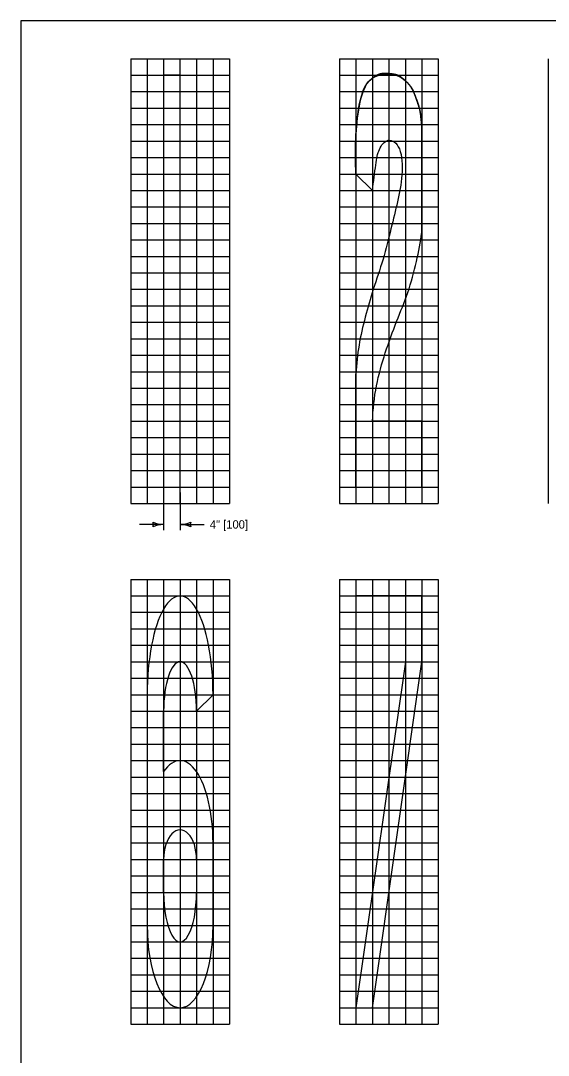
# Model space of a CAD drawing. Extents: x 49991.4 to 50021, y 49987.6 to 50011.4.
# Drawn here: x 50000.34 to 50004.12, y 50003.84 to 50011.26 of the extents above; entities that cross this region are included whole.
import ezdxf

# ---------------------------------------------------------------- set-up
doc = ezdxf.new("R2010")
doc.units = 0
for name, color, linetype in [('Level 1', 7, 'Continuous'), ('Level 2', 7, 'Continuous'), ('Level 3', 7, 'Continuous'), ('Level 9', 7, 'Continuous')]:
    doc.layers.add(name, color=color, linetype=linetype)

msp = doc.modelspace()

# ---------------------------------------------------------------- linework, layer by layer
at = {"layer": 'Level 1'}
for p, q in [((50001.3611, 50010.8724), (50001.3611, 50007.9192)), ((50001.4792, 50010.8724), (50001.3611, 50010.8724)), ((50001.4792, 50007.9192), (50001.4792, 50010.8724)), ((50003.2133, 50009.7442), (50003.2134, 50010.3999)), ((50002.7409, 50010.1636), (50002.859, 50010.0455)), ((50002.7409, 50008.7301), (50002.7409, 50007.9192)), ((50003.2134, 50008.3916), (50002.8591, 50008.3916)), ((50003.2134, 50007.9192), (50003.2134, 50008.3916)), ((50002.7409, 50007.9192), (50003.2134, 50007.9192)), ((50003.2134, 50007.1392), (50002.7409, 50007.1392)), ((50002.7409, 50007.1392), (50002.7409, 50006.6667)), ((50003.2134, 50006.6667), (50003.2134, 50007.1392)), ((50003.0953, 50006.6667), (50002.7409, 50004.1861)), ((50002.7409, 50006.6667), (50003.0953, 50006.6667)), ((50002.8591, 50004.1861), (50003.2134, 50006.6667)), ((50001.243, 50006.4304), (50001.243, 50004.7767)), ((50001.5973, 50006.3123), (50001.7155, 50006.4304)), ((50001.3611, 50005.8788), (50001.3611, 50006.3123)), ((50001.7155, 50004.7767), (50001.7155, 50005.3673)), ((50001.3611, 50005.0129), (50001.3611, 50005.2492)), ((50001.5973, 50005.2492), (50001.5973, 50005.0129)), ((50002.7409, 50004.1861), (50002.8591, 50004.1861))]:
    msp.add_line(p, q, dxfattribs=at)
msp.add_lwpolyline([(50008.6146, 50011.2628), (50000.3356, 50011.2628), (50000.3356, 50000.0624), (50008.6146, 50000.0624)], close=True, dxfattribs=at)
for centre, major_axis, ratio, start_param, end_param in [((50001.4792, 50006.4304), (0, -0.7087), 0.333309, 1.570796, 4.712389), ((50001.4792, 50006.3123), (0, 0.3544), 0.333309, 4.712389, 7.853866), ((50001.4792, 50005.3673), (0, -0.5906), 0.399971, 1.570796, 3.665191), ((50001.4792, 50005.2492), (0, 0.2125), 0.555853, 4.712389, 7.853982), ((50001.4792, 50005.0129), (0, 0.3544), 0.333309, 1.570796, 4.712389), ((50001.4792, 50004.7767), (0, 0.5906), 0.399971, 1.570838, 4.712389)]:
    msp.add_ellipse(centre, major_axis=major_axis, ratio=ratio, start_param=start_param, end_param=end_param, dxfattribs=at)
for points, degree in [([(50002.856, 50010.8496), (50002.7998, 50010.808), (50002.7555, 50010.6449), (50002.7428, 50010.4992), (50002.7393, 50010.4209)], 3), ([(50002.9807, 50010.883), (50002.9367, 50010.8868), (50002.8899, 50010.8746), (50002.856, 50010.8496)], 2), ([(50003.0955, 50010.832), (50003.0647, 50010.8602), (50003.024, 50010.8793), (50002.9807, 50010.883)], 2), ([(50003.1795, 50010.6859), (50003.1631, 50010.733), (50003.1393, 50010.7918), (50003.0955, 50010.832)], 2), ([(50003.2073, 50010.5672), (50003.2017, 50010.616), (50003.1931, 50010.647), (50003.1795, 50010.6859)], 2), ([(50003.2134, 50010.3999), (50003.2147, 50010.467), (50003.2122, 50010.524), (50003.2073, 50010.5672)], 2), ([(50002.7393, 50010.4209), (50002.7355, 50010.336), (50002.7355, 50010.2494), (50002.7409, 50010.1636)], 2), ([(50002.859, 50010.0455), (50002.8675, 50010.1052), (50002.8837, 50010.2485), (50002.9012, 50010.3398), (50002.9649, 50010.4307), (50003.068, 50010.3688), (50003.0785, 50010.1518), (50003.0402, 50009.9647), (50002.9935, 50009.7776), (50002.9386, 50009.5497), (50002.8617, 50009.3355), (50002.8067, 50009.1384), (50002.7577, 50008.9357), (50002.7448, 50008.8021), (50002.7409, 50008.7301)], 3), ([(50002.8591, 50008.3916), (50002.8627, 50008.475), (50002.8816, 50008.649), (50002.9489, 50008.8823), (50003.0319, 50009.1117), (50003.1174, 50009.3075), (50003.1776, 50009.5413), (50003.2041, 50009.6768), (50003.2133, 50009.7442)], 3)]:
    msp.add_open_spline(points, degree=degree, dxfattribs=at)
at = {"layer": 'Level 3'}
for p, q in [((50001.3611, 50007.8792), (50001.3611, 50007.6111)), ((50001.4792, 50007.8792), (50001.4792, 50007.6111)), ((50001.3611, 50007.6511), (50001.1877, 50007.6511)), ((50001.4792, 50007.6511), (50001.6526, 50007.6511))]:
    msp.add_line(p, q, dxfattribs=at)
for centre, radius, start, end in [((50001.3702, 50007.8733), 0.2223, 247.45601, 267.63952), ((50001.2329, 50007.6511), 0.0548, 342.13882, 17.86118), ((50001.3726, 50007.4184), 0.233, 92.82731, 112.07716), ((50001.4677, 50007.8838), 0.233, 272.82731, 292.07716), ((50001.47, 50007.429), 0.2223, 67.45601, 87.63952), ((50001.6074, 50007.6511), 0.0548, 162.13882, 197.86118)]:
    msp.add_arc(centre, radius, start, end, dxfattribs=at)
at = {"layer": 'Level 9'}
for p, q in [((50001.1249, 50010.9905), (50001.1249, 50007.8011)), ((50001.1249, 50010.9905), (50001.8335, 50010.9905)), ((50001.243, 50010.9905), (50001.243, 50007.8011)), ((50001.3611, 50010.9905), (50001.3611, 50007.8011)), ((50001.4792, 50007.8011), (50001.4792, 50010.9905)), ((50001.5973, 50010.9905), (50001.5973, 50007.8011)), ((50001.7154, 50010.9905), (50001.7154, 50007.8011)), ((50001.8335, 50010.9905), (50001.8335, 50007.8011)), ((50002.6228, 50010.9905), (50002.6228, 50007.8011)), ((50002.6228, 50010.9905), (50003.3315, 50010.9905)), ((50002.7409, 50010.9905), (50002.7409, 50007.8011)), ((50002.859, 50010.9905), (50002.859, 50007.8011)), ((50002.9771, 50010.9905), (50002.9771, 50007.8011)), ((50003.0953, 50010.9905), (50003.0953, 50007.8011)), ((50003.2134, 50010.9905), (50003.2134, 50007.8011)), ((50003.3315, 50010.9905), (50003.3315, 50007.8011)), ((50004.1207, 50010.9905), (50004.1207, 50007.8011)), ((50001.1248, 50010.8724), (50001.8336, 50010.8724)), ((50002.6228, 50010.8723), (50003.3315, 50010.8723)), ((50001.1248, 50010.7542), (50001.8336, 50010.7542)), ((50002.6228, 50010.7542), (50003.3315, 50010.7542)), ((50001.1248, 50010.6361), (50001.8336, 50010.6361)), ((50002.6228, 50010.6361), (50003.3315, 50010.6361)), ((50001.1248, 50010.518), (50001.8336, 50010.518)), ((50002.6228, 50010.518), (50003.3315, 50010.518)), ((50001.1248, 50010.3999), (50001.8336, 50010.3999)), ((50002.6228, 50010.3999), (50003.3315, 50010.3999)), ((50003.2134, 50010.3999), (50003.2133, 50009.7442)), ((50001.1248, 50010.2817), (50001.8336, 50010.2817)), ((50002.6228, 50010.2817), (50003.3315, 50010.2817)), ((50001.1248, 50010.1636), (50001.8336, 50010.1636)), ((50002.6228, 50010.1636), (50003.3315, 50010.1636)), ((50002.7409, 50010.1636), (50002.859, 50010.0455)), ((50001.1248, 50010.0455), (50001.8336, 50010.0455)), ((50002.6228, 50010.0455), (50003.3315, 50010.0455)), ((50001.1248, 50009.9274), (50001.8336, 50009.9274)), ((50002.6228, 50009.9274), (50003.3315, 50009.9274)), ((50001.1248, 50009.8092), (50001.8336, 50009.8092)), ((50002.6228, 50009.8092), (50003.3315, 50009.8092)), ((50001.1248, 50009.6911), (50001.8336, 50009.6911)), ((50002.6228, 50009.6911), (50003.3315, 50009.6911)), ((50001.1248, 50009.573), (50001.8336, 50009.573)), ((50002.6228, 50009.573), (50003.3315, 50009.573)), ((50001.1248, 50009.4549), (50001.8336, 50009.4549)), ((50002.6228, 50009.4549), (50003.3315, 50009.4549)), ((50001.1248, 50009.3367), (50001.8336, 50009.3367)), ((50002.6228, 50009.3367), (50003.3315, 50009.3367)), ((50001.1248, 50009.2186), (50001.8336, 50009.2186)), ((50002.6228, 50009.2186), (50003.3315, 50009.2186)), ((50001.1248, 50009.1005), (50001.8336, 50009.1005)), ((50002.6228, 50009.1005), (50003.3315, 50009.1005)), ((50001.1248, 50008.9824), (50001.8336, 50008.9824)), ((50002.6228, 50008.9824), (50003.3315, 50008.9824)), ((50001.1248, 50008.8642), (50001.8336, 50008.8642)), ((50002.6228, 50008.8642), (50003.3315, 50008.8642)), ((50001.1248, 50008.7461), (50001.8336, 50008.7461)), ((50002.6228, 50008.7461), (50003.3315, 50008.7461)), ((50002.7409, 50007.9192), (50002.7409, 50008.7301)), ((50001.1248, 50008.628), (50001.8336, 50008.628)), ((50002.6228, 50008.628), (50003.3315, 50008.628)), ((50001.1248, 50008.5099), (50001.8336, 50008.5099)), ((50002.6228, 50008.5099), (50003.3315, 50008.5099)), ((50001.1248, 50008.3917), (50001.8336, 50008.3917)), ((50002.6228, 50008.3917), (50003.3315, 50008.3917)), ((50003.2134, 50008.3916), (50002.8591, 50008.3916)), ((50003.2134, 50007.9192), (50003.2134, 50008.3916)), ((50001.1248, 50008.2736), (50001.8336, 50008.2736)), ((50002.6228, 50008.2736), (50003.3315, 50008.2736)), ((50001.1248, 50008.1555), (50001.8336, 50008.1555)), ((50002.6228, 50008.1555), (50003.3315, 50008.1555)), ((50001.1248, 50008.0374), (50001.8336, 50008.0374)), ((50002.6228, 50008.0374), (50003.3315, 50008.0374)), ((50001.1248, 50007.9192), (50001.8336, 50007.9192)), ((50001.3611, 50007.9192), (50001.4792, 50007.9192)), ((50002.6228, 50007.9192), (50003.3315, 50007.9192)), ((50002.7409, 50007.9192), (50003.2134, 50007.9192)), ((50001.1248, 50007.8011), (50001.8336, 50007.8011)), ((50002.6228, 50007.8011), (50003.3315, 50007.8011)), ((50001.1249, 50007.2573), (50001.1249, 50004.0679)), ((50001.1249, 50007.2573), (50001.8336, 50007.2573)), ((50001.243, 50007.2573), (50001.243, 50004.0679)), ((50001.3611, 50007.2573), (50001.3611, 50004.0679)), ((50001.4792, 50007.2573), (50001.4792, 50004.0679)), ((50001.5973, 50007.2573), (50001.5973, 50004.0679)), ((50001.7155, 50007.2573), (50001.7155, 50004.0679)), ((50001.8336, 50007.2573), (50001.8336, 50004.0679)), ((50002.6228, 50007.2573), (50002.6228, 50004.0679)), ((50002.6228, 50007.2573), (50003.3315, 50007.2573)), ((50002.7409, 50007.2573), (50002.7409, 50004.0679)), ((50002.8591, 50007.2573), (50002.8591, 50004.0679)), ((50002.9772, 50007.2573), (50002.9772, 50004.0679)), ((50003.0953, 50007.2573), (50003.0953, 50004.0679)), ((50003.2134, 50007.2573), (50003.2134, 50004.0679)), ((50003.3315, 50007.2573), (50003.3315, 50004.0679)), ((50001.1249, 50007.1392), (50001.8336, 50007.1392)), ((50002.6228, 50007.1392), (50003.3315, 50007.1392)), ((50001.1249, 50007.0211), (50001.8336, 50007.0211)), ((50002.6228, 50007.0211), (50003.3315, 50007.0211)), ((50001.1249, 50006.9029), (50001.8336, 50006.9029)), ((50002.6228, 50006.9029), (50003.3315, 50006.9029)), ((50001.1249, 50006.7848), (50001.8336, 50006.7848)), ((50002.6228, 50006.7848), (50003.3315, 50006.7848)), ((50001.1249, 50006.6667), (50001.8336, 50006.6667)), ((50002.6228, 50006.6667), (50003.3315, 50006.6667)), ((50001.1249, 50006.5486), (50001.8336, 50006.5486)), ((50002.6228, 50006.5486), (50003.3315, 50006.5486)), ((50001.1249, 50006.4304), (50001.8336, 50006.4304)), ((50002.6228, 50006.4304), (50003.3315, 50006.4304)), ((50001.1249, 50006.3123), (50001.8336, 50006.3123)), ((50002.6228, 50006.3123), (50003.3315, 50006.3123)), ((50001.1249, 50006.1942), (50001.8336, 50006.1942)), ((50002.6228, 50006.1942), (50003.3315, 50006.1942)), ((50001.1249, 50006.0761), (50001.8336, 50006.0761)), ((50002.6228, 50006.0761), (50003.3315, 50006.0761)), ((50001.1249, 50005.9579), (50001.8336, 50005.9579)), ((50002.6228, 50005.9579), (50003.3315, 50005.9579)), ((50001.1249, 50005.8398), (50001.8336, 50005.8398)), ((50002.6228, 50005.8398), (50003.3315, 50005.8398)), ((50001.1249, 50005.7217), (50001.8336, 50005.7217)), ((50002.6228, 50005.7217), (50003.3315, 50005.7217)), ((50001.1249, 50005.6036), (50001.8336, 50005.6036)), ((50002.6228, 50005.6036), (50003.3315, 50005.6036)), ((50001.1249, 50005.4854), (50001.8336, 50005.4854)), ((50002.6228, 50005.4854), (50003.3315, 50005.4854)), ((50001.1249, 50005.3673), (50001.8336, 50005.3673)), ((50002.6228, 50005.3673), (50003.3315, 50005.3673)), ((50001.1249, 50005.2492), (50001.8336, 50005.2492)), ((50002.6228, 50005.2492), (50003.3315, 50005.2492)), ((50001.1249, 50005.1311), (50001.8336, 50005.1311)), ((50002.6228, 50005.1311), (50003.3315, 50005.1311)), ((50001.1249, 50005.0129), (50001.8336, 50005.0129)), ((50002.6228, 50005.0129), (50003.3315, 50005.0129)), ((50001.1249, 50004.8948), (50001.8336, 50004.8948)), ((50002.6228, 50004.8948), (50003.3315, 50004.8948)), ((50001.1249, 50004.7767), (50001.8336, 50004.7767)), ((50002.6228, 50004.7767), (50003.3315, 50004.7767)), ((50001.1249, 50004.6586), (50001.8336, 50004.6586)), ((50002.6228, 50004.6586), (50003.3315, 50004.6586)), ((50001.1249, 50004.5404), (50001.8336, 50004.5404)), ((50002.6228, 50004.5404), (50003.3315, 50004.5404)), ((50001.1249, 50004.4223), (50001.8336, 50004.4223)), ((50002.6228, 50004.4223), (50003.3315, 50004.4223)), ((50001.1249, 50004.3042), (50001.8336, 50004.3042)), ((50002.6228, 50004.3042), (50003.3315, 50004.3042)), ((50001.1249, 50004.1861), (50001.8336, 50004.1861)), ((50002.6228, 50004.1861), (50003.3315, 50004.1861)), ((50001.1249, 50004.0679), (50001.8336, 50004.0679)), ((50002.6228, 50004.0679), (50003.3315, 50004.0679))]:
    msp.add_line(p, q, dxfattribs=at)
for points in [[(50002.7409, 50010.1636), (50002.7355, 50010.2494), (50002.7355, 50010.416), (50002.7555, 50010.6449), (50002.8125, 50010.8546), (50002.9826, 50010.8987), (50003.1226, 50010.8331), (50003.1827, 50010.6845), (50003.2093, 50010.5887), (50003.2147, 50010.467), (50003.2134, 50010.3999)], [(50002.859, 50010.0455), (50002.8675, 50010.1052), (50002.8837, 50010.2485), (50002.9012, 50010.3398), (50002.9649, 50010.4307), (50003.068, 50010.3688), (50003.0785, 50010.1518), (50003.0402, 50009.9647), (50002.9935, 50009.7776), (50002.9386, 50009.5497), (50002.8617, 50009.3355), (50002.8067, 50009.1384), (50002.7577, 50008.9357), (50002.7448, 50008.8021), (50002.7409, 50008.7301)], [(50002.8591, 50008.3916), (50002.8627, 50008.475), (50002.8816, 50008.649), (50002.9489, 50008.8823), (50003.0319, 50009.1117), (50003.1174, 50009.3075), (50003.1776, 50009.5413), (50003.2041, 50009.6768), (50003.2133, 50009.7442)]]:
    msp.add_open_spline(points, degree=3, dxfattribs=at)

# ---------------------------------------------------------------- texts
at = {"layer": 'Level 2'}
msp.add_text('4" [100] ', height=0.06, dxfattribs=at).set_placement((50001.6926, 50007.6211))

doc.saveas('drawing.dxf')
